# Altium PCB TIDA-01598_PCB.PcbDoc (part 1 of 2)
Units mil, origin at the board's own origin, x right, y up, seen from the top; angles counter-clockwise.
Board outline 5000 x 4300 mil, 4 copper layers (Top Layer, Power, Ground, Bottom Layer), stack 61.6 mil thick; 99 components, 31 nets, 235 pads, 61 vias.
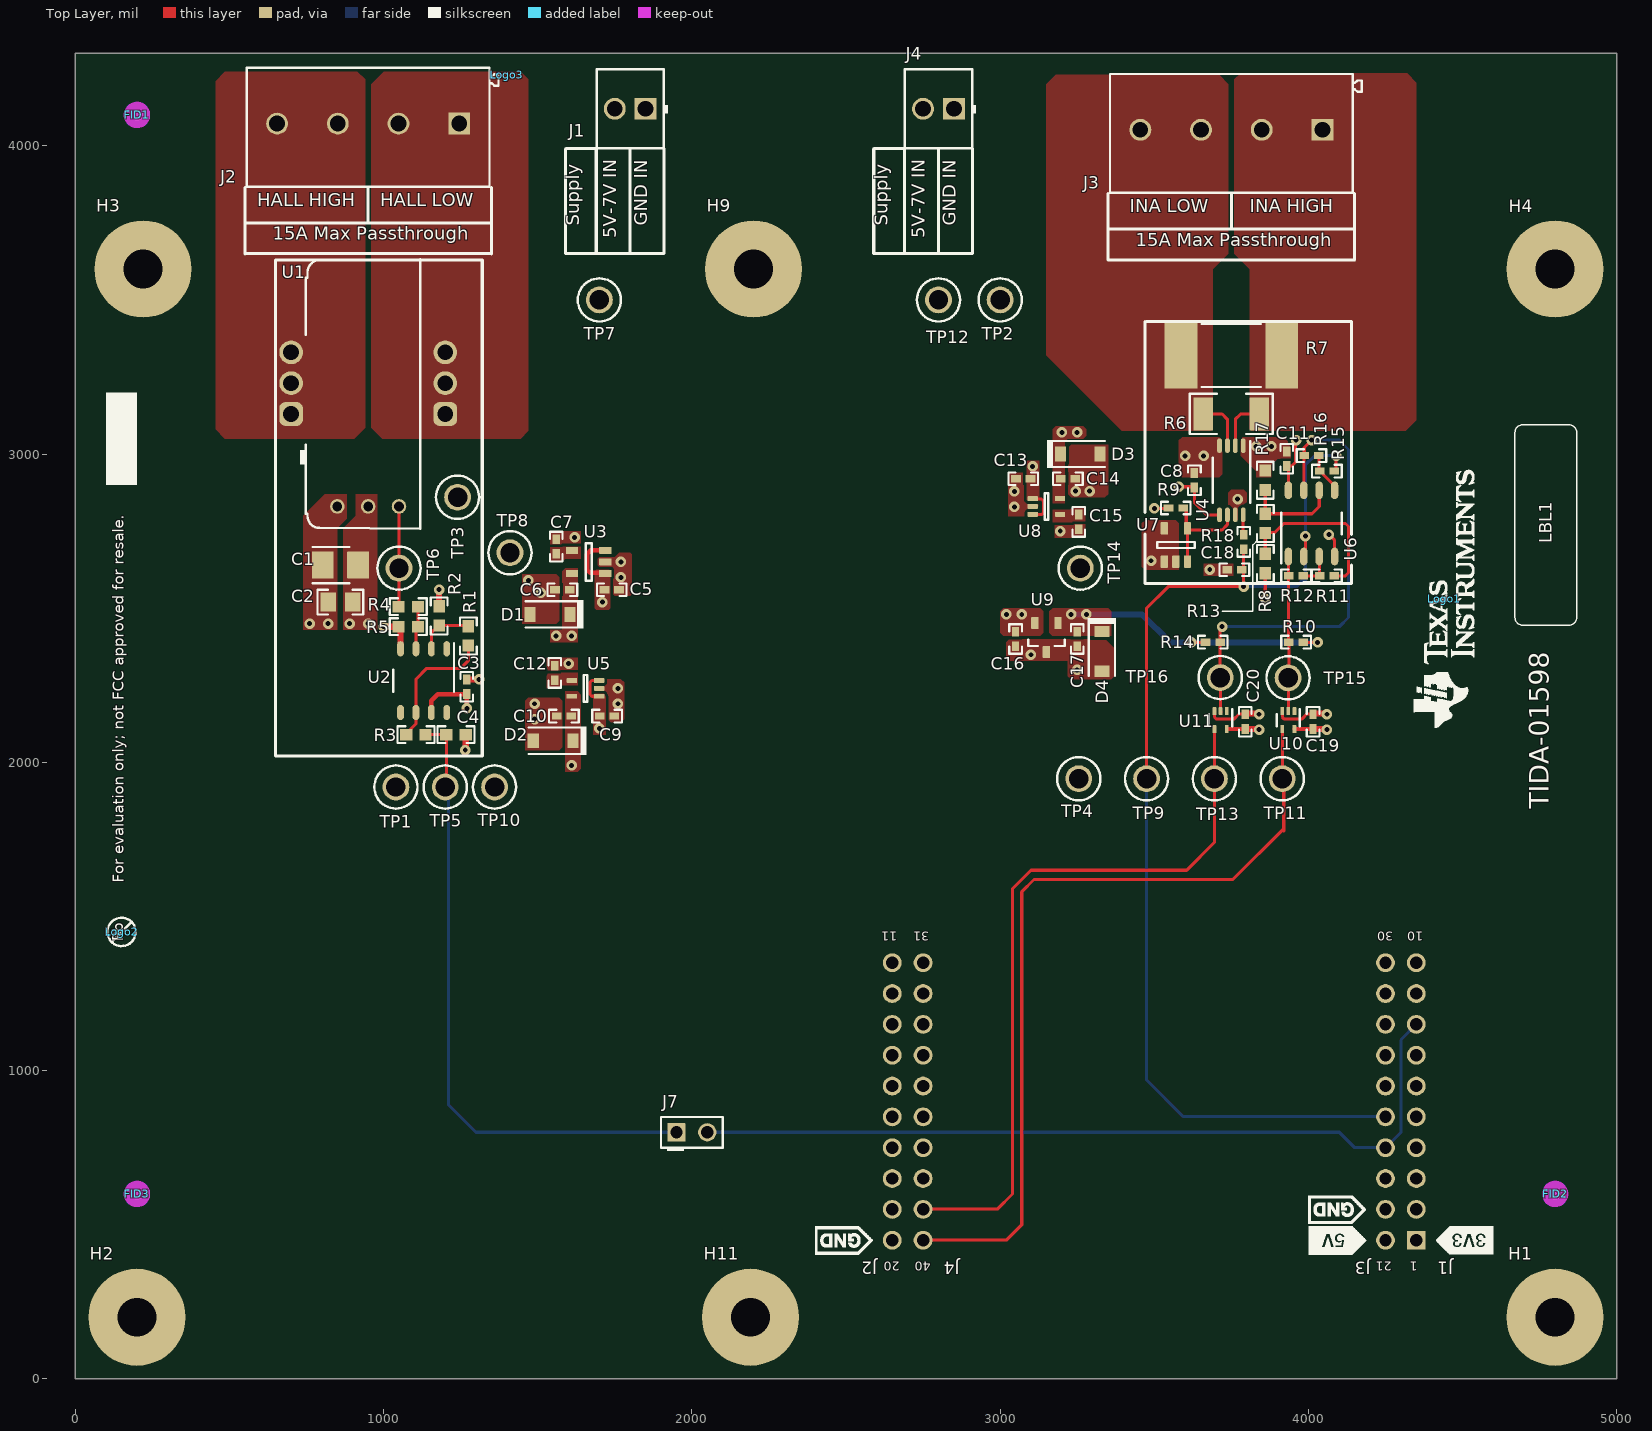
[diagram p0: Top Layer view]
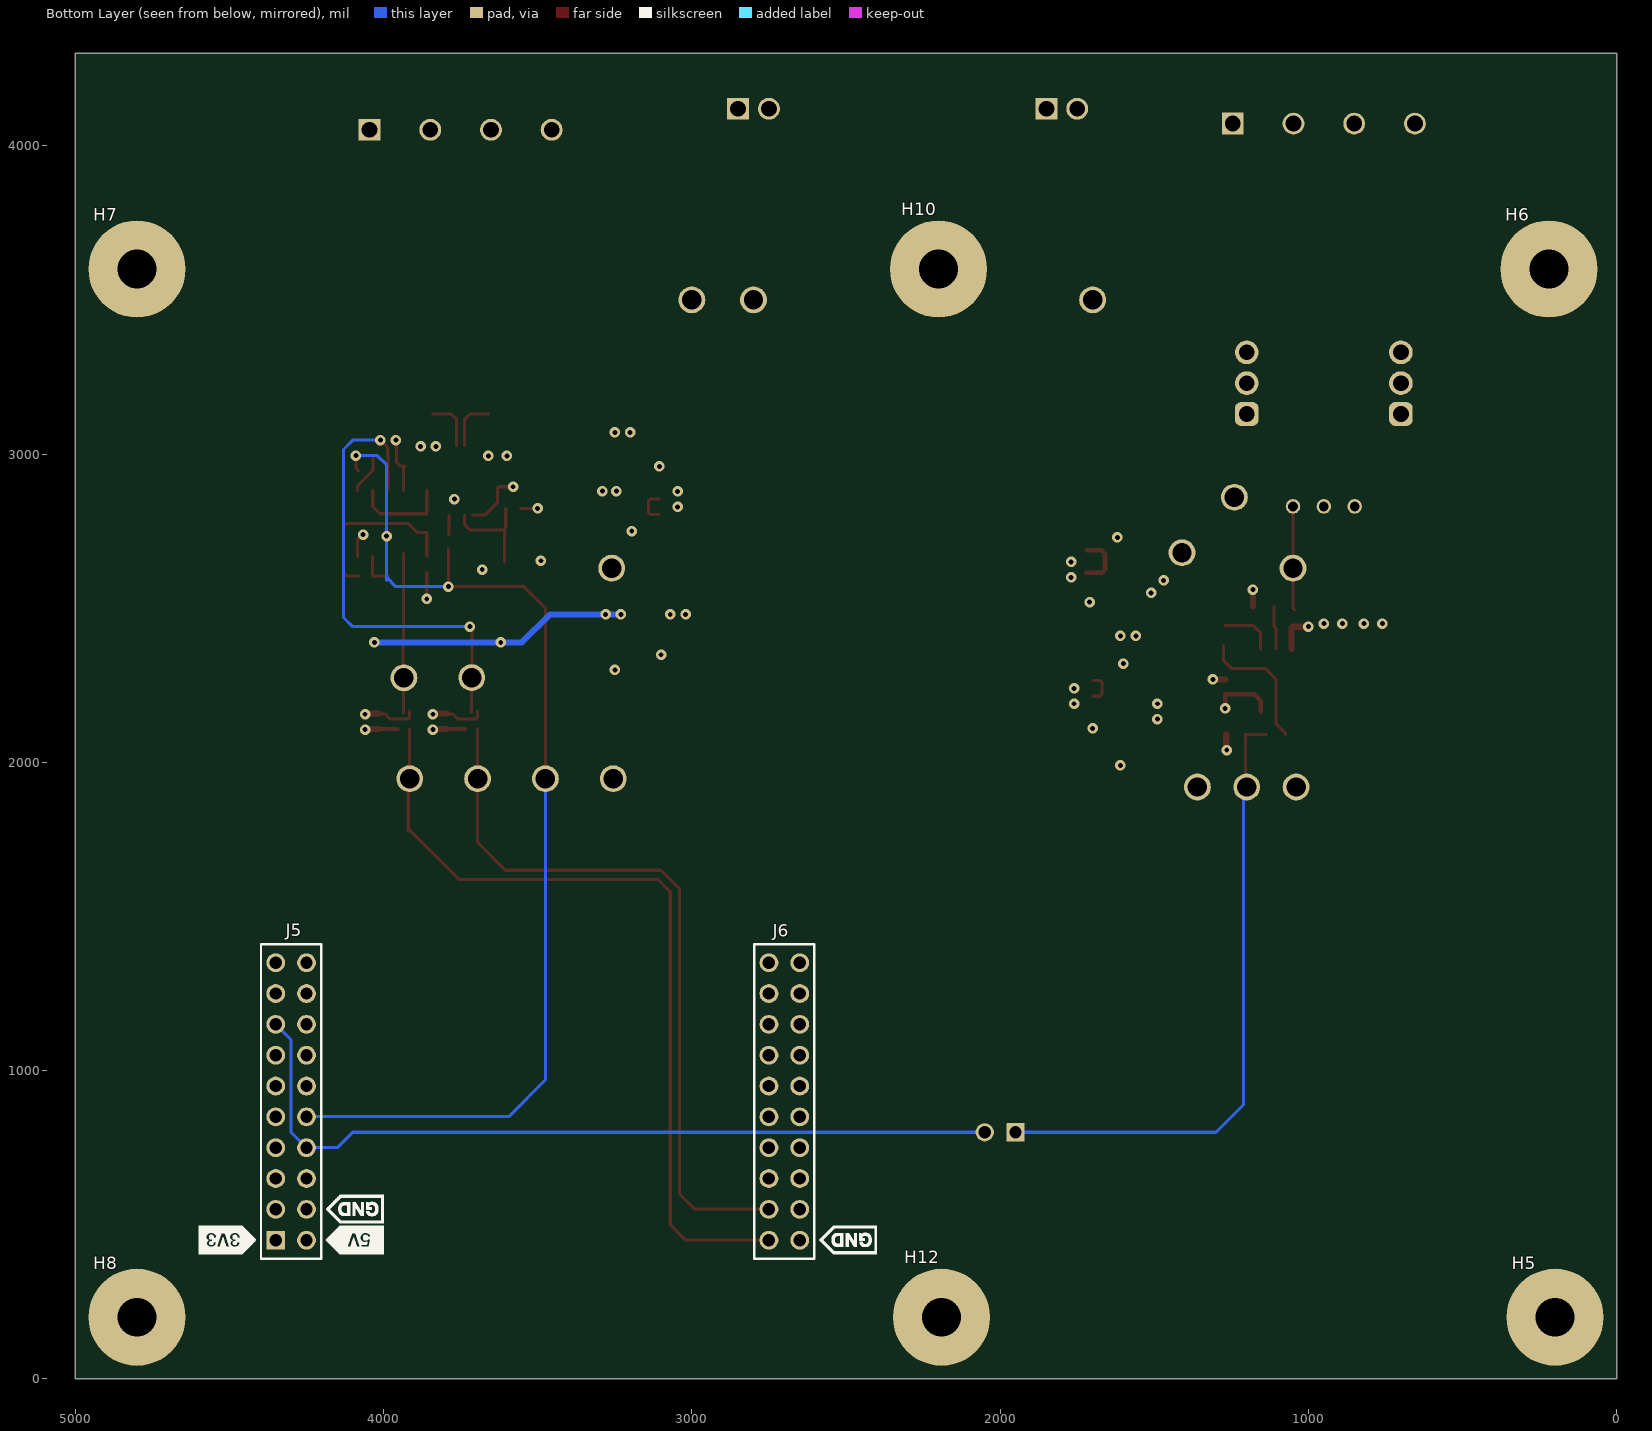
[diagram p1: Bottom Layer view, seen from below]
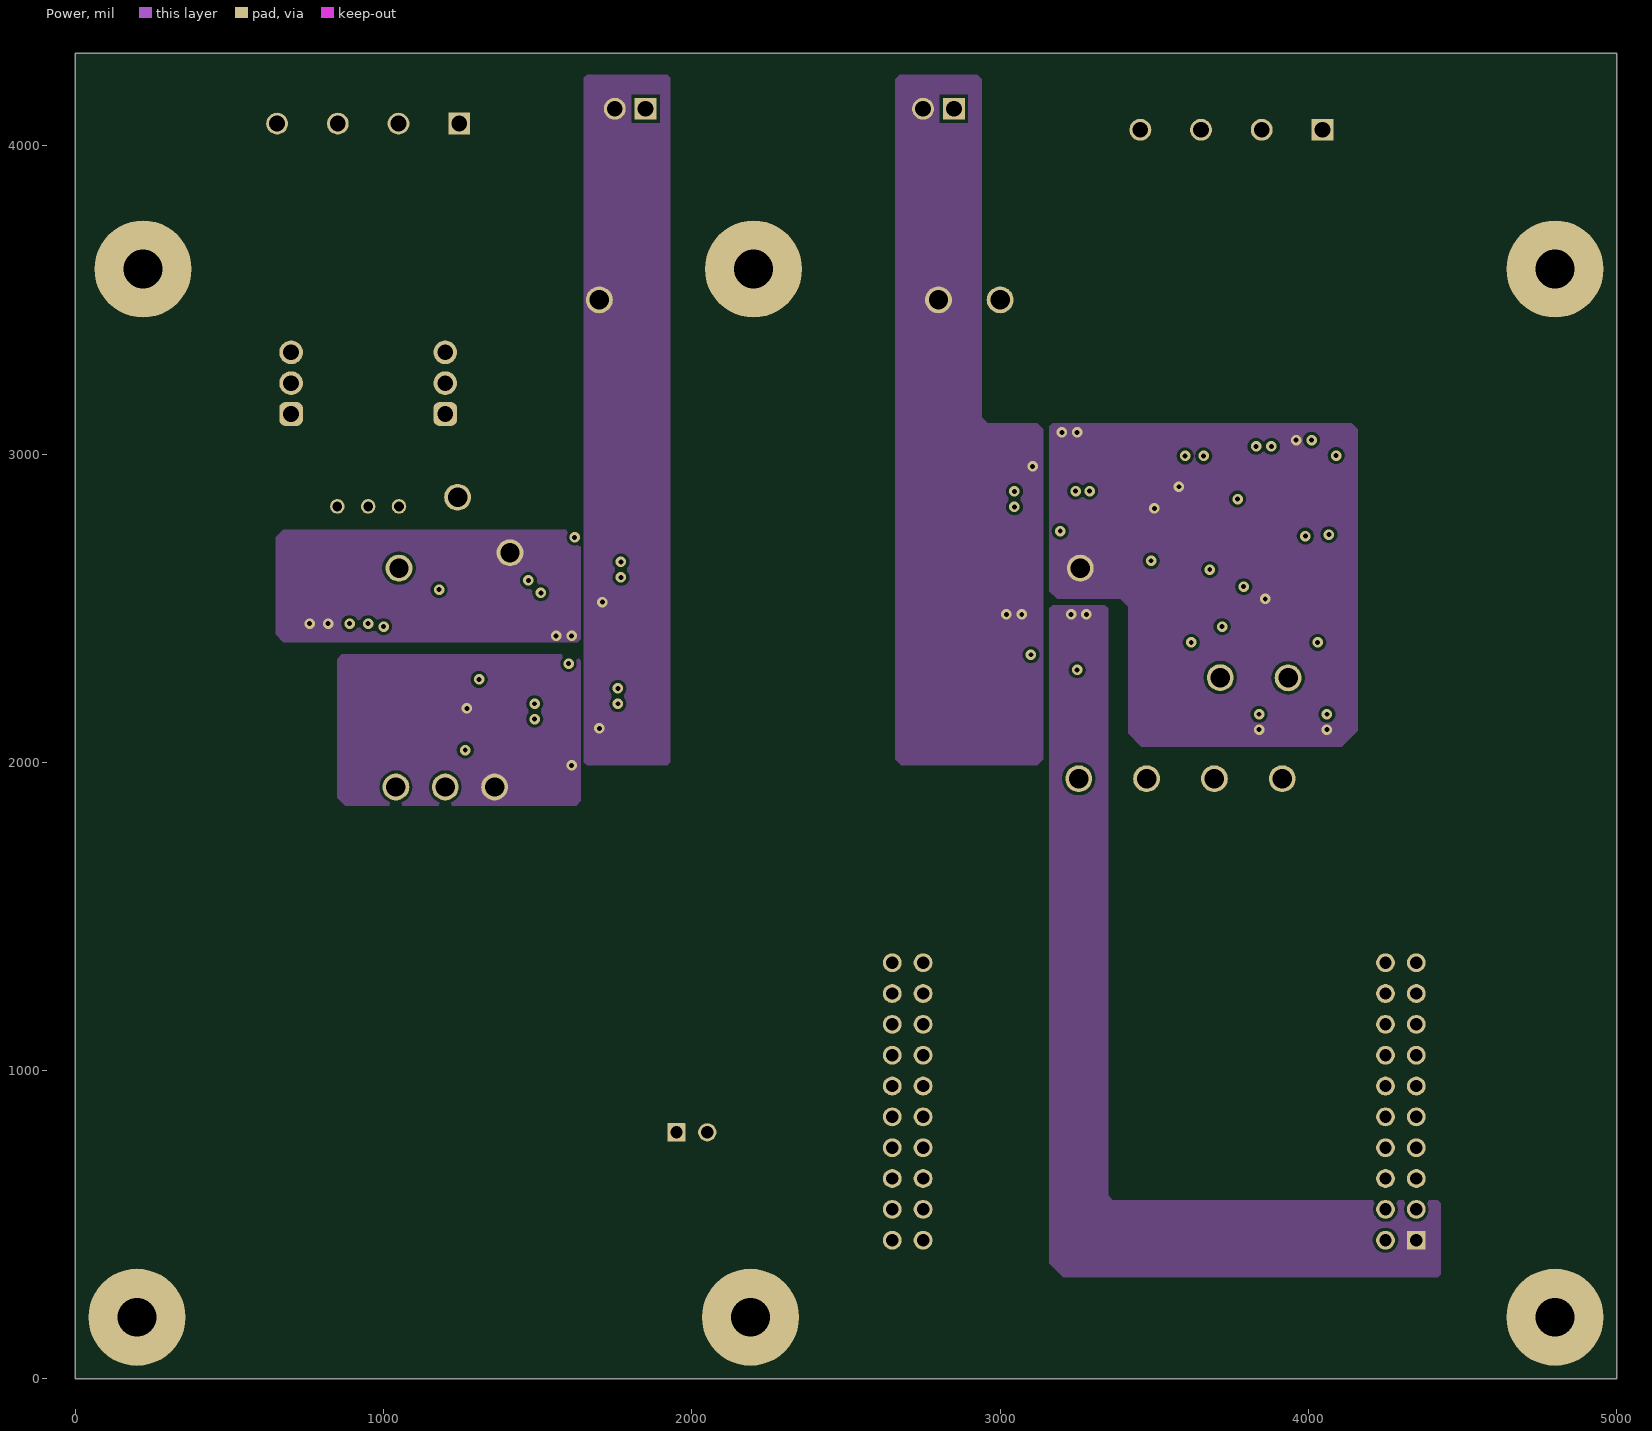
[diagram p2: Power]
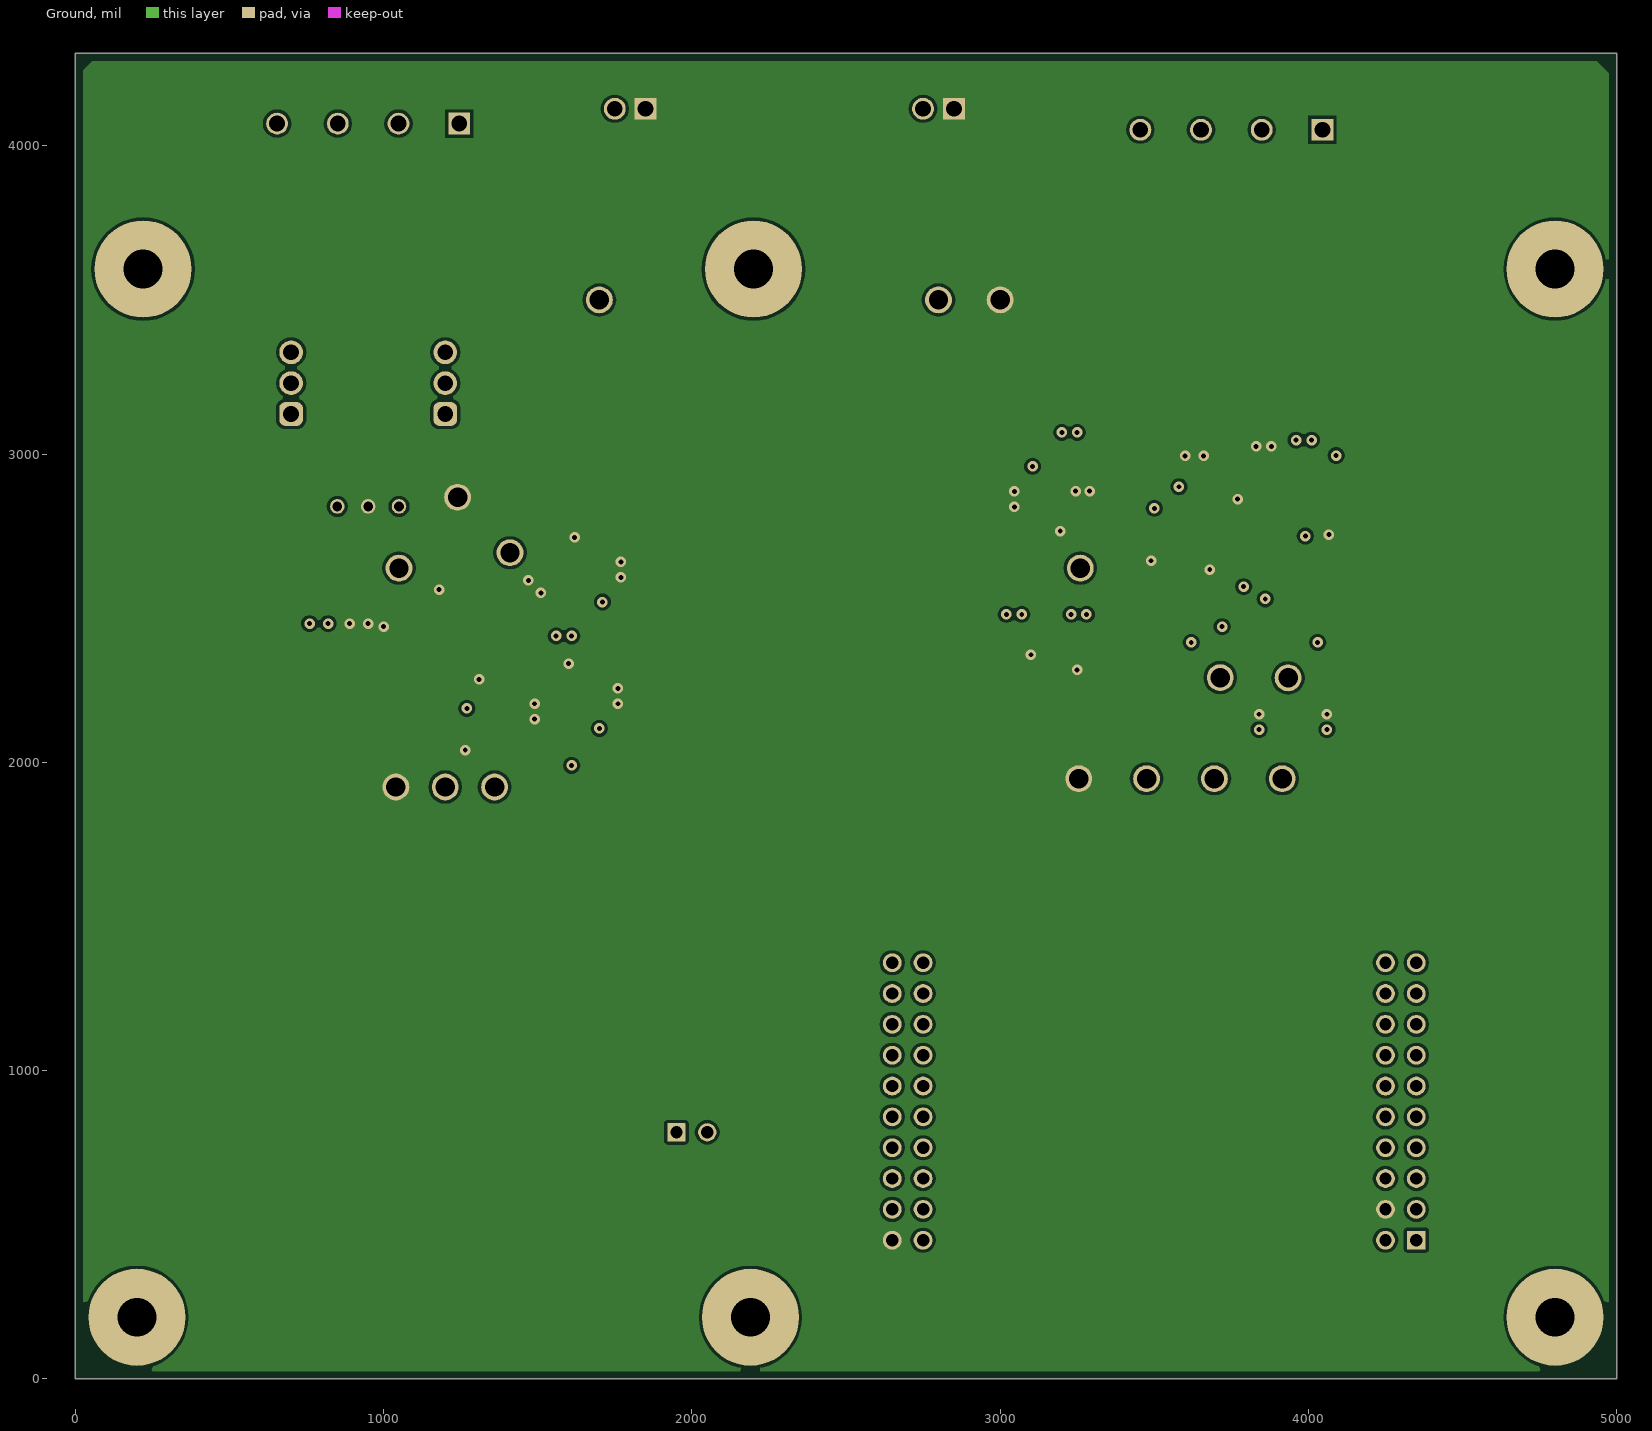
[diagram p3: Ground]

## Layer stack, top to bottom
Top Solder: solder mask 0.4, Solder Resist, Dk 3.5
Top Layer: signal copper 1.4
Dielectric 1: prepreg 8, FR-4, Dk 4.2
Power: signal copper 1.4
Dielectric 2: core 40, FR-4, Dk 4.2
Ground: signal copper 1.4
Dielectric 3: prepreg 8, FR-4, Dk 4.2
Bottom Layer: signal copper 1.4
Bottom Solder: solder mask 0.4, Solder Resist, Dk 3.5

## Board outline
0,0 0,4300 5000,4300 5000,0

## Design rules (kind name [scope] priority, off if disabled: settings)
AcuteAngle [All] p1: minimum=4.50000000000000E+0001 checktracksonly=FALSE
AssemblyTestPointUsage [All] p1: valid=2
BoardOutlineClearance BoardOutlineClearance_MountingHoles [OnCopper and InComponentClass('Mounting Holes')] p1: gap=40 ignorepadtopadclearanceinfootprint=FALSE
BoardOutlineClearance BoardOutlineClearance_Poly [OnCopper and IsPoly] p2: gap=25 ignorepadtopadclearanceinfootprint=FALSE
BoardOutlineClearance [OnCopper and Not InComponentClass('Logo') and not InComponentClass('FiducialMark') and not InRegion(1000,500,4000,800) and not InPoly] p3: gap=75 ignorepadtopadclearanceinfootprint=FALSE
Clearance Clearance_Keepouts [((IsTrack Or IsArc) And Not InPoly) And IsFree and IsKeepOut vs ((IsTrack Or IsArc) And Not InPoly) And IsFree and IsKeepOut] p1: gap=0 ignorepadtopadclearanceinfootprint=FALSE
Clearance Clearance_Poly [InPolygon] p2: gap=10 ignorepadtopadclearanceinfootprint=FALSE except(0: Arc-Hole Track-Hole SMDPad-Hole THPad-Hole Via-Hole Fill-Hole Poly-Hole Region-Hole Text-Hole)
Clearance Clearance_FiducialMark [IsKeepOut and InComponentClass('FiducialMark') vs IsPad and InComponentClass('FiducialMark')] p3: gap=0 ignorepadtopadclearanceinfootprint=FALSE
Clearance [All] p4: gap=7.87 ignorepadtopadclearanceinfootprint=FALSE except(0: Arc-Hole Track-Hole SMDPad-Hole THPad-Hole Via-Hole Fill-Hole Poly-Hole Region-Hole Text-Hole)
ComponentClearance ComponentClearance_MountingHoles_FiducialMarks [InComponentClass('Mounting Holes') vs InComponentClass('FiducialMark')] p1: gap=50 collisioncheckmode=3 verticalgap=10 showdistances=FALSE
ComponentClearance ComponentClearance_Shunt [InComponentClass('Header') vs InComponentClass('Shunt')] p2: gap=0 collisioncheckmode=3 verticalgap=0 showdistances=FALSE
ComponentClearance ComponentClearance_Logo [InComponentClass('Logo')] p3: gap=50 collisioncheckmode=3 verticalgap=10 showdistances=FALSE
ComponentClearance ComponentClearance_ScrewToNut [(HasFootprint('NY PMS 440 0025 PH')) vs (HasFootprint('Keystone_1902C'))] p4: gap=5 collisioncheckmode=3 verticalgap=10 showdistances=FALSE
ComponentClearance ComponentClearance_MountingHoles [InComponentClass('Mounting Holes')] p5: gap=250 collisioncheckmode=3 verticalgap=100000 showdistances=FALSE
ComponentClearance ComponentClearance_SmallPassives [HasFootprint('0201*') or HasFootprint('0402*') or HasFootprint('0508') or HasFootprint('0603*') or HasFootprint('0612') or HasFootprint('0805*') or HasFootprint('0815*') or HasFootprint('0830*') or HasFootprint('1206*') or HasFootprint('1210*') or HasFootprint('1808*') or HasFootprint('1812*') or HasFootprint('1825*') or HasFootprint('2010*') or HasFootprint('2220*') or HasFootprint('2225*') or HasFootprint('2512*') or HasFootprint('2728*') or HasFootprint('3518*') vs HasFootprint('0201*') or HasFootprint('0402*') or HasFootprint('0508') or HasFootprint('0603*') or HasFootprint('0612') or HasFootprint('0805*') or HasFootprint('0815*') or HasFootprint('0830*') or HasFootprint('1206*') or HasFootprint('1210*') or HasFootprint('1808*') or HasFootprint('1812*') or HasFootprint('1825*') or HasFootprint('2010*') or HasFootprint('2220*') or HasFootprint('2225*') or HasFootprint('2512*') or HasFootprint('2728*') or HasFootprint('3518*')] p6: gap=14.96 collisioncheckmode=3 verticalgap=10 showdistances=FALSE
ComponentClearance ComponentClearance_THtoSMT [IsThruComponent vs IsSMTComponent] p7: gap=40 collisioncheckmode=3 verticalgap=30 showdistances=FALSE
ComponentClearance ComponentClearance_THtoTH [IsThruComponent vs IsThruComponent] p8: gap=30 collisioncheckmode=3 verticalgap=30 showdistances=FALSE
ComponentClearance [All] p9: gap=30 collisioncheckmode=3 verticalgap=10 showdistances=FALSE
DiffPairsRouting [All] p1: maxlimit=100 minlimit=10 mostfreqgap=10 toplayer_minwidth=15 toplayer_maxwidth=15 toplayer_prefwidth=15 midlayer1_minwidth=15 midlayer1_maxwidth=15 midlayer1_prefwidth=15 midlayer2_minwidth=15 midlayer2_maxwidth=15 midlayer2_prefwidth=15 bottomlayer_minwidth=15 bottomlayer_maxwidth=15 bottomlayer_prefwidth=15 maxuncoupledlength=1000
FabricationTestPointUsage TestPointUsage [All] p1: valid=2 allowmultiple=FALSE
FabricationTestpoint Testpoint [All] p1: side=3 testpointundercomponent=TRUE minsize=40 maxsize=100 preferedsize=60 minholesize=0 maxholesize=40 preferedholesize=32 testpointgrid=1 allowsidetop=TRUE allowsidebottom=TRUE usegrid=TRUE gridtolerance=0.01
FanoutControl Fanout_LCC [IsLCC] p1: bgadir=Out bgaviamode=Centered fanoutstyle=Auto fanoutdirection=Alternating viagrid=1 // Fanout_LCC (Default Rule)
FanoutControl Fanout_BGA [IsBGA] p2: bgadir=Out bgaviamode=Centered fanoutstyle=Auto fanoutdirection=Alternating viagrid=1 // Fanout_BGA (Default Rule)
FanoutControl Fanout_Default [All] p4: bgadir=Out bgaviamode=Centered fanoutstyle=Auto fanoutdirection=Alternating viagrid=1 // Fanout_Default (Default Rule)
FanoutControl Fanout_Small [(CompPinCount < 5)] p5: bgadir=Out bgaviamode=Centered fanoutstyle=Auto fanoutdirection=OutThenIn viagrid=1 // Fanout_Small (Default Rule)
HoleSize [All] p1: absolutevalues=TRUE maxlimit=251 minlimit=7.87 maxpercent=80.000 minpercent=20.000
MinimumAnnularRing MinimumAnnularRing_ThermalPadVias [IsVia and InAnyComponent] p1: minimumring=5.91
MinimumAnnularRing [All] p2: minimumring=7.87
MinimumSolderMaskSliver MinimumSolderMaskSliver_Logo [InComponentClass('Logo') vs InComponentClass('Logo')] p1: minsoldermaskwidth=0.7
MinimumSolderMaskSliver [All] p2: minsoldermaskwidth=3.94
PlaneConnect [All] p1: planeconnectstyle=Relief reliefexpansion=10 reliefentries=4 reliefconductorwidth=10 reliefairgap=10
PolygonConnect [All] p1: connectstyle=Direct reliefconductorwidth=10 reliefentries=4 polygonreliefangle="90 Angle" airgapwidth=10
RoutingVias ThermalPadVias [IsVia and InAnyComponent] p1: holewidth=7.87 width=19.68 viastyle="Through Hole" minholewidth=7.87 minwidth=19.68 maxholewidth=12.99 maxwidth=23.62
RoutingVias [All] p2: holewidth=16 width=34 viastyle="Through Hole" minholewidth=7.87 minwidth=26 maxholewidth=40 maxwidth=65
SilkToBoardRegionClearance [Not ((IsComment or IsDesignator) And (Hide <> 'False')) and not InRegion(1000,500,4000,800)] p1:
SilkToSilkClearance SilkToSilkClearance_Pb-FreeLogo [(HasFootprint('Pb-Free_Overlay_Medium') OR HasFootprint('Pb-Free_Overlay_Small')) vs (HasFootprint('Pb-Free_Overlay_Medium') OR HasFootprint('Pb-Free_Overlay_Small'))] p1: silktosilkclearance=0
SilkToSilkClearance [All] p2: silktosilkclearance=4
SilkToSolderMaskClearance SilkToComponentPadClearance [(IsPad or IsFill or IsRegion) and InAnycomponent] p1: minsilkscreentomaskgap=5 clearancetoexposedcopper=TRUE
SilkToSolderMaskClearance "Silk to Solder Mask Opening" [All] p2: minsilkscreentomaskgap=4 clearancetoexposedcopper=FALSE
SolderMaskExpansion [All] p1: expansion=1.97
Width [All] p1: maxlimit=100 minlimit=6 preferedwidth=10 checkconnectedcopper=TRUE
15 further rules are at their usual default settings.

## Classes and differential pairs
component class Logo: Logo1
component class TIDA-01598_EVM_Hardware: FID1 FID2 FID3 H1 H2 H3 H4 H5 H6 H7 H8 H9 H10 H11 H12 LBL1 Logo1 Logo2 Logo3 ZZ1 ZZ2 ZZ3 ZZ4
component class FiducialMark: FID1 FID2 FID3
component class AssemblyNote: ZZ1 ZZ2 ZZ3 ZZ4
component class Label: LBL1
component class TIDA-01598_Main: C1 C2 C3 C4 C5 C6 C7 C8 C9 C10 C11 C12 C13 C14 C15 C16 C17 C18 C19 C20 D1 D2 D3 D4 J1 J2 J3 J4 J5 J6 J7 J8 R1 R2 R3 R4 R5 R6 R7 R8 R9 R10 R11 R12 R13 R14 R15 R16 R17 R18 TP1 TP2 TP3 TP4 TP5 TP6 TP7 TP8 TP9 TP10 TP11 TP12 TP13 TP14 TP15 TP16 U1 U2 U3 U4 U5 U6 U7 U8 U9 U10 U11
component class "Mounting Holes": H1 H2 H3 H4 H9 H11
component class Header: J7

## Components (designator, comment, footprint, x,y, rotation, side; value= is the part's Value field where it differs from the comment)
C1 "TAJB106K016RNJ" 3528-21 860,2640 r0 top value=10uF
C2 "C0805C104K4RACTU" 0805_HV 860,2520 r0 top value=0.1uF
C3 "885012205037" 0402 1270,2245 r90 top value=0.1uF
C4 "C0603C224J3RAC7867" 0603 1235,2090 r0 top value=0.22uF
C5 "C1005X5R1E105K050BC" 0402 1740,2560 r0 top value=1uF
C6 "C1005X5R1E105K050BC" 0402 1580,2560 r180 top value=1uF
C7 "GRM155R61A103KA01D" 0402 1560,2700 r90 top value=0.01uF
C8 "885012205037" 0402 3630,2915 r90 top value=0.1uF
C9 "C1005X5R1E105K050BC" 0402 1725,2150 r0 top value=1uF
C10 "C1005X5R1E105K050BC" 0402 1585,2150 r180 top value=1uF
C11 "885012205037" 0402 3930,2985 r90 top value=0.1uF
C12 "GRM155R61A103KA01D" 0402 1555,2290 r90 top value=0.01uF
C13 "C1005X5R1E105K050BC" 0402 3075,2920 r180 top value=1uF
C14 "C1005X5R1E105K050BC" 0402 3220,2920 r0 top value=1uF
C15 "GRM155R61A103KA01D" 0402 3255,2780 r270 top value=0.01uF
C16 "885012205037" 0402 3050,2400 r270 top value=0.1uF
C17 "885012205037" 0402 3250,2400 r270 top value=0.1uF
C18 "C0402C102J3RACTU" 0402 3760,2625 r180 top value=1000pF
C19 "885012205037" 0402 4015,2132 r90 top value=0.1uF
C20 "885012205037" 0402 3795,2132 r90 top value=0.1uF
D1 "MMSZ5232B-7-F" SOD-123 1540,2480 r180 top value=5.6V
D2 "MMSZ4685T1G" SOD-123 1550,2070 r180 top value=3.6V
D3 "MMSZ4685T1G" SOD-123 3260,3000 r0 top value=3.6V
D4 "MMSZ4685T1G" SOD-123 3330,2360 r270 top value=3.6V
FID1 "Fiducial" Fiducial10-20 200,4100 r0 top
FID2 "Fiducial" Fiducial10-20 4800,600 r0 top
FID3 "Fiducial" Fiducial10-20 200,600 r0 top
H1 "NY PMS 440 0025 PH" "NY PMS 440 0025 PH" 4800,200 r90 top
H2 "NY PMS 440 0025 PH" "NY PMS 440 0025 PH" 200,200 r90 top
H3 "NY PMS 440 0025 PH" "NY PMS 440 0025 PH" 220,3600 r180 top
H4 "NY PMS 440 0025 PH" "NY PMS 440 0025 PH" 4800,3600 r90 top
H5 "1902C" Keystone_1902C 200.35,199.77 r180 bottom
H6 "1902C" Keystone_1902C 220.36,3600 r180 bottom
H7 "1902C" Keystone_1902C 4800.36,3600 r180 bottom
H8 "1902C" Keystone_1902C 4800.36,200 r180 bottom
H9 "NY PMS 440 0025 PH" "NY PMS 440 0025 PH" 2200,3600 r90 top
H10 "1902C" Keystone_1902C 2199.02,3600 r90 bottom
H11 "NY PMS 440 0025 PH" "NY PMS 440 0025 PH" 2190,200 r90 top
H12 "1902C" Keystone_1902C 2189.02,200 r90 bottom
J1 "OSTVN02A150" On-Shore_OSTVN02A150 1800,4120 r180 top
J2 "1715048" Phoenix_1715048 950,4060 r180 top
J3 "1715048" Phoenix_1715048 3750,4040 r180 top
J4 "OSTVN02A150" On-Shore_OSTVN02A150 2800,4120 r180 top
J5 "SSQ-110-03-T-D" BoosterPack_40pin_J1J3 4300,900 r0 bottom
J6 "SSQ-110-03-T-D" BoosterPack_40pin_J2J4 2700,900 r0 bottom
J7 "PEC02SAAN" CONN_PEC02SAAN 2000,800 r0 top
LBL1 "Size: 0.65\" x 0.20 \"" Label_650x200 4770,2770 r90 top
Logo1 "Texas Instruments" TI_Stacked_Overlay_Small 4440,2530 r90 top
Logo2 "Pb-Free Symbol" Pb-Free_Overlay_Small 150,1450 r90 top
Logo3 "FCC disclaimer" FCC_disclaimer 1400,4230 r0 top
R1 "ERJ-3EKF3303V" 0603 1275,2410 r270 top value=330k
R2 "ERJ-3EKF4993V" 0603 1180,2475 r270 top value=499k
R3 "CRCW060368R1FKEA" 0603 1105,2090 r0 top value=68.1
R4 "ERJ-3EKF4993V" 0603 1080,2505 r0 top value=499k
R5 "ERJ-3EKF3303V" 0603 1080,2440 r0 top value=330k
R6 "PMR50HZPFV4L00" 2010 3750,3130 r0 top value=0.004
R7 "WSLP39212L000FEA" RC3921 3750,3320 r0 top value=0.002
R8 "RT0603BRD07196KL" 0603 3860,2645 r270 top value=196k
R9 "CRCW040210K0DHEDP" 0402 3570,2825 r180 top value=10.0k
R10 "ERJ-2RKF3301X" 0402 3960,2390 r0 top value=3.30k
R11 "CRCW040210K0DHEDP" 0402 4060,2605 r180 top value=10.0k
R12 "CRCW04023M32FKED" 0402 3960,2605 r180 top value=3.32Meg
R13 "RG1608P-2493-B-T5" 0603 3860,2775 r270 top value=249k
R14 "ERJ-2RKF3301X" 0402 3690,2390 r180 top value=3.30k
R15 "CRCW040210K0DHEDP" 0402 4060,2945 r180 top value=10.0k
R16 "CRCW04023M32FKED" 0402 4010,2995 r180 top value=3.32Meg
R17 "RT0603BRD07102KL" 0603 3860,2915 r90 top value=102k
R18 "RC0402FR-07100RL" 0402 3790,2715 r270 top value=100
TP1 "5011" Keystone5011 1040,1919.96 r90 top
TP2 "5011" Keystone5011 3000,3500 r90 top
TP3 "5011" Keystone5011 1240,2860 r90 top
TP4 "5011" Keystone5011 3255,1947 r90 top
TP5 "5012" Keystone5012 1200,1919.96 r90 top
TP6 "5012" Keystone5012 1050,2630 r90 top
TP7 "5010" Keystone5010 1700,3500 r90 top
TP8 "5010" Keystone5010 1410,2680 r90 top
TP9 "5012" Keystone5012 3475,1947 r90 top
TP10 "5010" Keystone5010 1360,1920 r90 top
TP11 "5012" Keystone5012 3915,1947 r90 top
TP12 "5010" Keystone5010 2800,3500 r90 top
TP13 "5012" Keystone5012 3695,1947 r90 top
TP14 "5010" Keystone5010 3260,2630 r90 top
TP15 "5012" Keystone5012 3934,2274 r0 top
TP16 "5012" Keystone5012 3714,2275 r0 top
U1 "LTS 15-NP" LEM_LTS 950,3230 r90 top
U2 "OPA350UA/2K5" D0008A_L 1130,2265 r270 top
U3 "LP2985-50DBVR" DBV0005A_N 1665,2650 r180 top
U4 "INA240A2PWR" PW0008A_L 3750,2915 r270 top
U5 "TPS71733DCKT" DCK0005A_N 1655,2240 r180 top
U6 "LMV393M/NOPB" D0008A_N 4010,2775 r90 top
U7 "TLV431BCDBVR" DBV0005A_N 3570,2705 r90 top
U8 "TPS71733DCKT" DCK0005A_N 3150,2830 r0 top
U9 "TLV76033DBZR" DBZ0003A_N 3150,2405 r270 top
U10 "SN74LVC1G17DRLR" DRL0005A 3935,2137 r270 top
U11 "SN74LVC1G17DRLR" DRL0005A 3715,2137 r270 top
ZZ1 "This Assembly Note is for PCB labels only" AssemblyNoteLabel 245,5758 r0 top
ZZ2 "These assemblies are ESD sensitive, ESD precautions shall be observed." AssemblyNote 245,5649.11 r0 top
ZZ3 "These assemblies must be clean and free from flux and all contaminants. Use of no clean flux is not acceptable." AssemblyNote 245,5560.56 r0 top
ZZ4 "These assemblies must comply with workmanship standards IPC-A-610 Class 2, unless otherwise specified." AssemblyNote 245,5472 r0 top

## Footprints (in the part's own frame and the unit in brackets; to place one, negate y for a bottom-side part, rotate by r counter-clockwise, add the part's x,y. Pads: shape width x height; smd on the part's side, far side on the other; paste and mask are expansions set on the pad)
0402 [mm] "0402 from SM-752 data"
  rect 0.8x0.6 smd: 1(-0.6,0) 2(0.6,0)
  silkscreen extent -1.22,-0.52 1.22,0.52, body extent -0.55,-0.3 0.55,0.3, height 0.6
0603 [mm] "0603 from SM-752 data"
  rect 1x0.95 smd: 1(-0.8,0) 2(0.8,0)
  silkscreen extent -1.52,-0.69 1.52,0.69, body extent -0.87,-0.47 0.87,0.47, height 1
0805_HV [mil] "0805 with 30mil clearance between pads"
  rect 50x63 smd: 1(-40,0) 2(40,0)
  silkscreen extent -74,-40 74,40, body extent -43,-29 43,29, height 57
2010 [mm] "Chip Capacitor, Body 5.08x2.54mm, IPC Medium Density"
  rect 1.6x2.7 smd: 1(-2.3,0) 2(2.3,0)
  silkscreen extent -3.42,-1.65 3.42,1.65, body extent -2.73,-1.45 2.73,1.45, height 1.66
3528-21 [mm] "Medium Density IPC, based on Kemet datasheet 2016-10-20"
  rrect6% 1.8x2.23 smd: 1(-1.46,0) 2(1.46,0)
  silkscreen extent -2.29,-1.5 0.76,1.5, body extent -1.85,-1.5 1.85,1.5, height 2.12
AssemblyNote [mil] "Assembly Note"
AssemblyNoteLabel [mil] "Assembly Note for PCB Labels"
BoosterPack_40pin_J1J3 [mm] "Receptacle, 2.54mm, 10x2, TH"
  rrect6% 1.55x1.55 hole 1.02: 1(1.27,11.43)
  round 1.55 hole 1.02: 2(1.27,8.89) 3(1.27,6.35) 4(1.27,3.81) 5(1.27,1.27) 6(1.27,-1.27) 7(1.27,-3.81) 8(1.27,-6.35) 9(1.27,-8.89) 10(1.27,-11.43) 21(-1.27,11.43) 22(-1.27,8.89) 23(-1.27,6.35) 24(-1.27,3.81) 25(-1.27,1.27) 26(-1.27,-1.27) 27(-1.27,-3.81) 28(-1.27,-6.35) 29(-1.27,-8.89) 30(-1.27,-11.43)
  silkscreen extent -7.62,-12.95 7.62,12.95, body extent -2.48,-12.95 2.48,12.95, height 8.51
BoosterPack_40pin_J2J4 [mm] "Receptacle, 2.54mm, 10x2, TH"
  round 1.55 hole 1.02: 11(-1.27,-11.43) 12(-1.27,-8.89) 13(-1.27,-6.35) 14(-1.27,-3.81) 15(-1.27,-1.27) 16(-1.27,1.27) 17(-1.27,3.81) 18(-1.27,6.35) 19(-1.27,8.89) 20(-1.27,11.43) 31(1.27,-11.43) 32(1.27,-8.89) 33(1.27,-6.35) 34(1.27,-3.81) 35(1.27,-1.27) 36(1.27,1.27) 37(1.27,3.81) 38(1.27,6.35) 39(1.27,8.89) 40(1.27,11.43)
  silkscreen extent -7.62,-12.95 2.48,12.95, body extent -2.48,-12.95 2.48,12.95, height 8.51
CONN_PEC02SAAN [mm] "SULLINS"
  rrect7% 1.5x1.5 hole 1.016: 1(-1.27,0)
  round 1.5 hole 1.016: 2(1.27,0)
  silkscreen extent -2.54,-1.52 2.54,1.27, body extent -2.54,-1.27 2.54,1.27, height 8.38
D0008A_L [mm] "SOIC, 8-Leads, Body 4.9x3.9mm, Pitch 1.27mm, IPC High Density"
  oval 1.25x0.55 smd: 1(-2.625,1.905) 2(-2.625,0.635) 3(-2.625,-0.635) 4(-2.625,-1.905) 5(2.625,-1.905) 6(2.625,-0.635) 7(2.625,0.635) 8(2.625,1.905)
  silkscreen extent -3.1,-2.5 0.9,2.5, body extent -3,-2.45 3,2.45, height 1.63
D0008A_N [mm] "SOIC, 8-Leads, Body 4.9x3.9mm, Pitch 1.27mm, IPC Medium Density"
  oval 1.45x0.6 smd: 1(-2.725,1.905) 2(-2.725,0.635) 3(-2.725,-0.635) 4(-2.725,-1.905) 5(2.725,-1.905) 6(2.725,-0.635) 7(2.725,0.635) 8(2.725,1.905)
  silkscreen extent -3.3,-2.5 0.9,2.5, body extent -3,-2.45 3,2.45, height 1.63
DBV0005A_N [mm] "SOT23, 5-Leads, Body 2.9x1.6mm, Pitch 0.95mm, Lead Span 2.8mm, IPC Medium Density"
  rrect17% 1x0.6 smd: 1(-1.375,0.95) 2(-1.375,0) 3(-1.375,-0.95) 4(1.375,-0.95) 5(1.375,0.95)
  silkscreen extent -0.25,-1.55 0.25,1.55, body extent -1.42,-1.46 1.42,1.46, height 1.09
DBZ0003A_N [mm] "SOT23, 3-Leads, Body 2.9x1.3mm, Pitch 0.95mm, Lead Span 2.4mm, IPC Medium Density"
  rrect17% 1x0.6 smd: 1(-1.2,0.95) 2(-1.2,-0.95) 3(1.2,0)
  silkscreen extent 0.2,-1.5 0.7,1.5, body extent -1.26,-1.46 1.26,1.46, height 0.98
DCK0005A_N [mm] "SOT353, 5-Leads, Body 2x1.3mm, Pitch 0.65mm, Lead Span 2.1mm, IPC Medium Density"
  rrect25% 0.85x0.4 smd: 1(-1.125,0.65) 2(-1.125,0) 3(-1.125,-0.65) 4(1.125,-0.65) 5(1.125,0.65)
  silkscreen extent -0.15,-1.1 0.15,1.1, body extent -1.14,-1 1.14,1, height 0.95
DRL0005A [mm] "SOTFL, 5-Flat Leads, Body 1.2x1.6x0.6mm, Pitch 0.5mm, TI recommended"
  rrect33% 0.67x0.3 smd: 1(-0.74,0.5) 2(-0.74,0) 3(-0.74,-0.5) 4(0.74,-0.5) 5(0.74,0.5)
  silkscreen extent -0.9,-0.95 0.5,0.95, body extent -0.85,-0.85 0.85,0.85, height 0.62
FCC_disclaimer [mil]
Fiducial10-20 [mm]
  round 1 smd mask+0.5: 1(0,0)
  Top Layer keep-out circle w1.178: c0,0 r0.5
Keystone5010 [mil] "Keystone Multipurpose loops"
  round 87 hole 63: 1(0,0)
  silkscreen extent -70,-70 70,70, body extent -63,-63 63,62, height 319
Keystone5011 [mil] "Keystone Multipurpose loops"
  round 87 hole 63: 1(0,0)
  silkscreen extent -70,-70 70,70, body extent -63,-63 63,62, height 319
Keystone5012 [mil] "Keystone Multipurpose loops"
  round 87 hole 63: 1(0,0)
  silkscreen extent -70,-70 70,70, body extent -63,-63 63,62, height 319
Keystone_1902C [mil] "Hex Standoff, 4-40 threaded, nylon"
  round 1 on Mech4: 0(0,0)
  body extent -145,-126 146,126, height 501
Label_650x200 [mil] "Thermal Transfer Label"
  silkscreen extent -325,-100 325,100, body extent -325,-100 325,100, height 1
LEM_LTS [mm] "TH, 9-Leads, Body 22.2x10mm"
  rrect50% 1.95x1.95 hole 1.3: 1(-2.54,6.35) 6(-2.54,-6.35)
  round 1.95 hole 1.3: 2(0,6.35) 3(2.54,6.35) 4(2.54,-6.35) 5(0,-6.35)
  round 1.2 hole 0.8: 7(-10.16,-2.54) 8(-10.16,0) 9(-10.16,2.54)
  silkscreen extent -12,-4.3 10.2,5.6, body extent -12,-6.75 10.2,6.75, height 24
"NY PMS 440 0025 PH" [mm] "4-40 nylon screw and mounting hole"
  round 8 hole 3.2: 1(0,0)
  body extent -3.3,-3.3 3.3,3.3, height 2.69
On-Shore_OSTVN02A150 [mm] "Terminal Block, 2.54mm, 2-pole, Brass, TH"
  rect 1.8x1.8 hole 1.3: 1(-1.27,0)
  round 1.8 hole 1.3: 2(1.27,0)
  silkscreen extent -3.1,-3.25 2.77,3.25, body extent -2.77,-3.25 2.77,3.25, height 8.51
Pb-Free_Overlay_Small [mil]
  silkscreen extent -46,-46 46,46
Phoenix_1715048 [mm] "Terminal Block, 5mm, 4x1, TH"
  rect 1.8x1.8 hole 1.3: 1(-7.5,-0.3)
  round 1.8 hole 1.3: 2(-2.5,-0.3) 3(2.5,-0.3) 4(7.5,-0.3)
  silkscreen extent -10.74,-4.9 10,4.9, body extent -10.74,-4.9 10,4.9, height 14.3
PW0008A_L [mm] "TSOP, 8-Leads, Body 3x4.4mm, Pitch 0.65mm, IPC High Density"
  oval 1.2x0.4 smd: 1(-2.85,0.975) 2(-2.85,0.325) 3(-2.85,-0.325) 4(-2.85,-0.975) 5(2.85,-0.975) 6(2.85,-0.325) 7(2.85,0.325) 8(2.85,0.975)
  silkscreen extent -3.2,-1.55 1.85,1.55, body extent -3.21,-1.5 3.21,1.5, height 1.2
RC3921 [mm] "RESISTOR, SMD, 3921"
  rect 2.7x5.45 smd mask+0.102: 1(-4.15,0) 2(4.15,0)
  silkscreen extent -2.45,-2.6 2.45,2.6, body extent -5,-2.6 5,2.6, height 0.93
SOD-123 [mm] "On Semi recommended land pattern"
  rect 0.915x1.22 smd: 1(-1.637,0) 2(1.637,0)
  silkscreen extent -2.74,-1.17 2.03,1.17, body extent -1.93,-0.9 1.93,0.9, height 1.35
TI_Stacked_Overlay_Small [mil]
  silkscreen extent -418,-98 418,98

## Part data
C1: library part CMP-0011561-2, "CAP, TA, 10 uF, 16 V, +/- 10%, 2.8 ohm, SMD", Cap_Case=3528-21, Manufacturer=AVX, Supplier Part Number 1=478-1673-1-ND, Tolerance_%=10%, Value1="2.8 ohm", Value2=16V, ValueDisplayed=10uF
C2: "CAP, CERM, 0.1 µF, 16 V,+/- 10%, X7R, 0805", Cap_Case=0805, Manufacturer=Kemet, Supplier Part Number 1=399-1167-1-ND, TempCo=X7R, Tolerance_%=10, Value1="0.064 ohm", Value2=16V, ValueDisplayed=0.1µF
C3 C8 C11 C16 C17 C19 C20: "CAP, CERM, 0.1 µF, 16 V,+/- 10%, X7R, 0402", Cap_Case=0402, Manufacturer="Wurth Elektronik", Supplier Part Number 1=732-7532-1-ND, TempCo=X7R, Tolerance_%=10, Value2=16V, ValueDisplayed=0.1µF
C4: library part CMP-0006902-5, "CAP, CERM, 0.22 uF, 25 V, +/- 5%, X7R, 0603", Cap_Case=0603, Manufacturer=Kemet, Supplier Part Number 1=399-9967-1-ND, TempCo=X7R, Tolerance_%=5%, Value1=Unknown, Value2=25V, ValueDisplayed=0.22uF
C5 C6 C9 C10 C13 C14: "CAP, CERM, 1 µF, 25 V,+/- 10%, X5R, 0402", Cap_Case=0402, Manufacturer=TDK, Supplier Part Number 1=445-9066-1-ND, TempCo=X5R, Tolerance_%=10, Value2=25V, ValueDisplayed=1µF
C7 C12 C15: "CAP, CERM, 0.01 µF, 10 V,+/- 10%, X5R, 0402", Cap_Case=0402, Manufacturer=MuRata, Supplier Part Number 1=GRM155R61A103KA01D-ND, TempCo=X5R, Tolerance_%=10, Value2=10V, ValueDisplayed=0.01µF
C18: library part CMP-0006234-2, "CAP, CERM, 1000 pF, 25 V, +/- 5%, X7R, 0402", Cap_Case=0402, Manufacturer=Kemet, Supplier Part Number 1=399-7752-1-ND, TempCo=X7R, Tolerance_%=5%, Value1=Unknown, Value2=25V, ValueDisplayed=1000pF
D1: library part CMP-0005803-1, "Diode, Zener, 5.6 V, 500 mW, SOD-123", Manufacturer="Diodes Inc.", Power_W=500mW, Supplier Part Number 1=MMSZ5232B-FDICT-ND, Value1=0.5W
D2 D3 D4: library part CMP-0005782-1, "Diode, Zener, 3.6 V, 500 mW, SOD-123", Manufacturer="ON Semiconductor", Power_W=500mW, Supplier Part Number 1=MMSZ4685T1GOSCT-ND, Value1=0.5W
FID1 FID2 FID3: "Fiducial mark.  There is nothing to buy or mount.", Manufacturer=N/A
H1 H2 H3 H4 H9 H11: "Machine Screw, Round, #4-40 x 1/4, Nylon, Philips panhead", DigiKeyPartNumber=H542-ND, Manufacturer="B&F Fastener Supply"
H5 H6 H7 H8 H10 H12: "Standoff, Hex, 0.5\"L #4-40 Nylon", Alternate Manufacturer=-, Manufacturer=Keystone, Supplier Part Number 1=1902CK-ND
J1 J4: library part CMP-0075076-1, "Terminal Block, 2.54mm, 2x1, Brass, TH", Manufacturer="On-Shore Technology", Supplier Part Number 1=ED10561-ND
J2 J3: library part CMP-0055526-1, "Terminal Block, 5mm, 4x1, R/A,TH", Color=Green, Current_A=17.5A, Manufacturer="Phoenix Contact", Supplier Part Number 1=277-1260-ND, Voltage_V=400V
J5: library part CMP-0003837-1, "Receptacle, 2.54mm, 10x2, Tin, TH", Alternate Manufacturer="Major League Electronics", Alternate PartNumber=CRD-081413-A-G, Manufacturer=Samtec, Supplier Part Number 1=SAM1204-10-ND
J6: library part CMP-0078266-1, "Receptacle, 2.54mm, 10x2, Tin, TH", Alternate Manufacturer="Major League Electronics", Alternate PartNumber=CRD-081413-A-G, Manufacturer=Samtec, Supplier Part Number 1=SAM1204-10-ND
J7: library part CMP-0002337-1, "Header, 100mil, 2x1, Tin, TH", Color=Black, Current_A=3A, Manufacturer="Sullins Connector Solutions", Supplier Part Number 1=S1012E-02-ND, Voltage_V=1.8kV
LBL1: library part THT-14-423-10, "Thermal Transfer Printable Labels, 0.650\" W x 0.200\" H - 10,000 per roll", Manufacturer=Brady, Supplier Part Number 1=97C5133
Logo1: library part TI_Logo, "Texas Instrument Corporate Signature"
Logo2: library part Pb-Free
Logo3: library part FCC_disclaimer, "FCC_disclaimer"
R1 R5: library part CMP-0022697-2, "RES, 330 k, 1%, 0.1 W, AEC-Q200 Grade 0, 0603", Manufacturer=Panasonic, Power_W=100mW, Supplier Part Number 1=P330KHCT-ND, TempCo="100 ppm/C", Tolerance_%=1%, Value2=0.1W, Value_Code=330k
R2 R4: library part CMP-0022706-2, "RES, 499 k, 1%, 0.1 W, AEC-Q200 Grade 0, 0603", Manufacturer=Panasonic, Power_W=100mW, Supplier Part Number 1=P499KHCT-ND, TempCo="100 ppm/C", Tolerance_%=1%, Value2=0.1W, Value_Code=499k
R3: library part CMP-0022553-3, "RES, 68.1, 1%, 0.1 W, 0603", Manufacturer=Vishay-Dale, Power_W=100mW, Supplier Part Number 1=541-68.1HCT-ND, TempCo="100 ppm/C", Tolerance_%=1%, Value2=0.1W, Value_Code=68R1, ValueDisplayed=68.1
R6: library part CMP-0016545-2, "RES, 0.004, 1%, 1 W, 2010", Manufacturer=Rohm, Power_W=1W, Supplier Part Number 1=RHM.004ASCT-ND, TempCo="100 ppm/C", Tolerance_%=1%, Value_Code=4L000, ValueDisplayed=0.004
R7: library part WSLP39213L000FEB, "RES 0.002 OHM 1% 5W 3921", Manufacturer="VISHAY DALE", Supplier Part Number 1=WSLP39212L000FEA-ND
R8: library part CMP-0023850-3, "RES, 196 k, 0.1%, 0.1 W, 0603", Manufacturer="Yageo America", Power_W=100mW, TempCo="25 ppm/C", Tolerance_%=0.1%, Value2=0.1W, Value_Code=196k
R9 R11 R15: "RES, 10.0 k, 0.5%, 0.063 W, 0402", Manufacturer=Vishay-Dale, Power_W=0.063, Supplier Part Number 1=541-10KAVCT-ND, TempCo="50 ppm/C", Tolerance_%=0.5, Value1=0.5%, Value2=0.063W, Value_Code=10k0, ValueDisplayed=10.0k
R10 R14: "RES, 3.30 k, 1%, 0.1 W, AEC-Q200 Grade 0, 0402", Manufacturer=Panasonic, Power_W=0.1, Supplier Part Number 1=P3.30KLCT-ND, TempCo="100 ppm/C", Tolerance_%=1, Value1=1%, Value2=0.1W, Value_Code=3k30, ValueDisplayed=3.30k
R12 R16: "RES, 3.32 M, 1%, 0.063 W, 0402", Manufacturer=Vishay-Dale, Power_W=0.063, Supplier Part Number 1=541-3.32MLCT-ND, TempCo="100 ppm/C", Tolerance_%=1, Value1=1%, Value2=0.063W, Value_Code=3M32, ValueDisplayed=3.32M
R13: library part CMP-0023490-3, "RES, 249 k, 0.1%, 0.1 W, 0603", Manufacturer="Susumu Co Ltd", Power_W=100mW, Supplier Part Number 1=RG16P249KBCT-ND, TempCo="25 ppm/C", Tolerance_%=0.1%, Value2=0.1W, Value_Code=249k
R17: library part CMP-0023634-3, "RES, 102 k, 0.1%, 0.1 W, 0603", Manufacturer="Yageo America", Power_W=100mW, TempCo="25 ppm/C", Tolerance_%=0.1%, Value2=0.1W, Value_Code=102k
R18: library part CMP-0026722-1, "RES, 100, 1%, 0.063 W, 0402", Manufacturer="Yageo America", Power_W=63mW, Supplier Part Number 1=311-100LRCT-ND, TempCo="100 ppm/C", Tolerance_%=1%, Value2=0.063W, Value_Code=100R, ValueDisplayed=100
TP1 TP2 TP3 TP4: library part CMP-0055148-1, "Test Point, Multipurpose, Black, TH", Color=Black, Manufacturer=Keystone, Supplier Part Number 1=36-5011-ND
TP5 TP6 TP9 TP11 TP13 TP15 TP16: library part CMP-0055149-1, "Test Point, Multipurpose, White, TH", Color=White, Manufacturer=Keystone, Supplier Part Number 1=36-5012-ND
TP7 TP8 TP10 TP12 TP14: library part CMP-0055147-1, "Test Point, Multipurpose, Red, TH", Color=Red, Manufacturer=Keystone, Supplier Part Number 1=36-5010-ND
U1: library part CMP-0078305-1, "Current Transducer, TH", Manufacturer=LEM, Supplier Part Number 1=398-1001-ND
U2: library part CMP-0040981-2, "High-Speed, Single-Supply, Rail-to-Rail Operational Amplifier MicroAmplifier(TM) Series, 2.7 to 5.5 V, -40 to 85 degC, 8-pin SOIC (D8), Green (RoHS & no Sb/Br)", Manufacturer="Texas Instruments", Total Supply Voltage(Max)(+5V is 5, +/-5V is 10)=5.5, Total Supply Voltage(Min)(+5V is 5, +/-5V is 10)=2.7
U3: library part CMP-0036298-1, "Single Output Low Noise LDO, 150 mA, Fixed 5 V Output, 1.5% Tolerance, 2.2 to 16 V Input, Low IQ, 5-Pin SOT-23 (DBV), -40 to 125 degC, Green (RoHS & no Sb/Br), Tape and Reel", Manufacturer="Texas Instruments", Operating Temperature Range (degC)="-40 to 125"
U4: library part CMP-0075735-1, "High/Low Side, Bi-Directional Zero-Drift Current Sense Amp w/ Enhanced PWM Rejection, PW0008A (TSSOP-8)", Alternate Manufacturer="Texas Instruments", Alternate PartNumber=INA240A2PW
U5 U8: library part CMP-0035674-1, "Single Output High PSRR LDO, 150 mA, Fixed 3.3 V Output, 2.5 to 6.5 V Input, with Low IQ, 5-pin SC70 (DCK), -40 to 85 degC, Green (RoHS & no Sb/Br)", Manufacturer="Texas Instruments"
U6: library part CMP-0068190-2, "Dual General Purpose, Low Voltage, Tiny Pack Comparator, 8-pin Narrow SOIC, Pb-Free", Manufacturer="Texas Instruments"
U7: library part CMP-0032938-1, "Low-Voltage Adjustable Precision Shunt Regulator, 15 mA, 0 to 70 degC, 5-pin SOT-23 (DBV), Green (RoHS & no Sb/Br)", Manufacturer="Texas Instruments", Rating=Catalog, Temp Coeff(Max)(ppm/ degree C)=129
U9: library part CMP-0074893-1, "100-mA, 30-V, Fixed-Output, Linear-Voltage Regulator, DBZ0003A (SOT-23-3)", Alternate Manufacturer="Texas Instruments", Alternate PartNumber=TLV76033DBZT
U10 U11: library part CMP-0051707-3, "Single Schmitt-Trigger Buffer, DRL0005A, LARGE T&R", Alternate Manufacturer="Texas Instruments", F @ Nom Voltage(Max)(Mhz)=150, Generic Part Number=SN74LVC1G17, ICC @ Nom Voltage(Max)(mA)=0.01, Operating Temperature Range(C)="-40 to 125,-40 to 85", Rating=Catalog, tpd @ Nom Voltage(Max)(ns)=11,6.5,5.5,5, Voltage(Nom)(V)=1.8,2.5,3.3,5
ZZ1: library part AssemblyNoteLabel
ZZ2 ZZ3 ZZ4: library part AssemblyNote, "This Assembly Note will show in the PcbDoc and associated outputs"

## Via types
v1: diameter 34, hole 16, Top Layer to Bottom Layer, tented top, 61 vias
